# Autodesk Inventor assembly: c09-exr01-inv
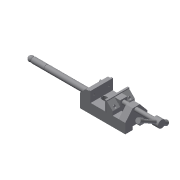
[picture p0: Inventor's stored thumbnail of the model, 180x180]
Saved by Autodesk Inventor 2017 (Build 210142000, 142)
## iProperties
Created: 2011-07
Part Number: c09-exr01-inv
Document SubType Name: Assembly
Designer: CadCim
Author: CadCim
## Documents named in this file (9)
- D:\New folder\New folder (3)\Inventor_2016_Exr\c09_inv_2016_exr\c09_Inv\c09_exr01_inv\Drill Press Vice\c09-exr01-inv.iam
- D:\New folder\New folder (3)\Inventor_2016_Exr\c09_inv_2016_exr\c09_Inv\c09_exr01_inv\Drill Press Vice\Base.ipt
- D:\New folder\New folder (3)\Inventor_2016_Exr\c09_inv_2016_exr\c09_Inv\c09_exr01_inv\Drill Press Vice\Jaw Face.ipt
- D:\New folder\New folder (3)\Inventor_2016_Exr\c09_inv_2016_exr\c09_Inv\c09_exr01_inv\Drill Press Vice\Movable Jaw.ipt
- D:\New folder\New folder (3)\Inventor_2016_Exr\c09_inv_2016_exr\c09_Inv\c09_exr01_inv\Drill Press Vice\Safety Handle.ipt
- D:\New folder\New folder (3)\Inventor_2016_Exr\c09_inv_2016_exr\c09_Inv\c09_exr01_inv\Drill Press Vice\Clamp Screw.ipt
- D:\New folder\New folder (3)\Inventor_2016_Exr\c09_inv_2016_exr\c09_Inv\c09_exr01_inv\Drill Press Vice\Clamp Screw Handle.ipt
- D:\New folder\New folder (3)\Inventor_2016_Exr\c09_inv_2016_exr\c09_Inv\c09_exr01_inv\Drill Press Vice\Handle Stop.ipt
- D:\New folder\New folder (3)\Inventor_2016_Exr\c09_inv_2016_exr\c09_Inv\c09_exr01_inv\Drill Press Vice\Cap Screw.ipt
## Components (13 placed, 8 different names)
1. Base:1 — Insert:3, Insert:9, Insert:10, Mate:8, Mate:9, Mate:12, Mate:13
2. Jaw Face:1 — Mate:10, Mate:11, Mate:12
3. Movable Jaw:1 — Mate:3, Insert:4, Insert:11, Insert:12, Mate:9, Mate:13, Mate:15
4. Safety Handle:1 — Insert:3
5. Clamp Screw:1 — Mate:3, Insert:4, Mate:4, Mate:6, Mate:8
6. Clamp Screw Handle:1 — Mate:4, Insert:7, Insert:8
7. Jaw Face:2 — Mate:14, Mate:15
8. Handle Stop:1 — Insert:7, Mate:6
9. Handle Stop:2 — Insert:8
10. Cap Screw:1 — Insert:12
11. Cap Screw:2 — Insert:11, Mate:14
12. Cap Screw:3 — Insert:10, Mate:11
13. Cap Screw:4 — Insert:9, Mate:10
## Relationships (19: Mate 11, Insert 8)
- Insert:3: Base:1 ↔ Safety Handle:1
- Mate:3: Movable Jaw:1 ↔ Clamp Screw:1
- Insert:4: Movable Jaw:1 ↔ Clamp Screw:1
- Mate:4: Clamp Screw:1 ↔ Clamp Screw Handle:1
- Insert:7: Clamp Screw Handle:1 ↔ Handle Stop:1
- Insert:8: Clamp Screw Handle:1 ↔ Handle Stop:2
- Mate:6: Clamp Screw:1 ↔ Handle Stop:1
- Insert:9: Base:1 ↔ Cap Screw:4
- Insert:10: Base:1 ↔ Cap Screw:3
- Insert:11: Movable Jaw:1 ↔ Cap Screw:2
- Insert:12: Movable Jaw:1 ↔ Cap Screw:1
- Mate:8: Base:1 ↔ Clamp Screw:1
- Mate:9: Base:1 ↔ Movable Jaw:1
- Mate:10: Jaw Face:1 ↔ Cap Screw:4
- Mate:11: Jaw Face:1 ↔ Cap Screw:3
- Mate:12: Base:1 ↔ Jaw Face:1
- Mate:13: Base:1 ↔ Movable Jaw:1
- Mate:14: Jaw Face:2 ↔ Cap Screw:2
- Mate:15: Movable Jaw:1 ↔ Jaw Face:2
